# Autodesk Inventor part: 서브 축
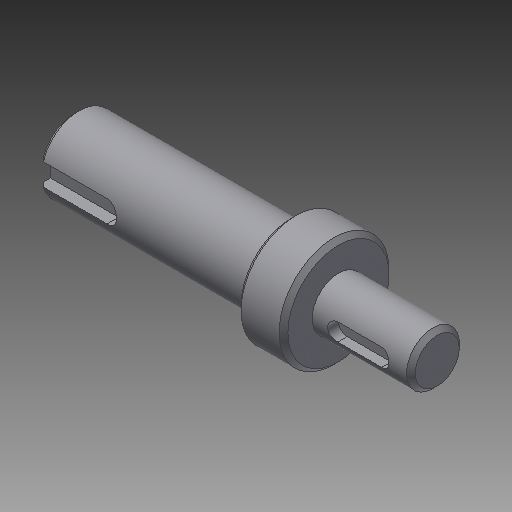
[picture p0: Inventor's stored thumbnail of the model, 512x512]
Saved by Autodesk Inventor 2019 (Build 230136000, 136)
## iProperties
Created: 2014-10
Part Number: 서브 축
Document SubType Name: Modeling
Designer: KYOUNG IL JANG
Density: 1 g/cm^3
Mass: 19.9624 g
Surface Area: 57.7178 cm^2
Volume: 19.9624 cm^3
Material: 강철, 연강
Appearance: 금속-강(스테인리스, 브러시됨)
Author: SeoGD™ [www.esajin.kr]
Revision Number: 1
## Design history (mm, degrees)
sketch "스케치1"
  geometry: L1 (-16.331, 0)-(-98.831, 0); L2 (-16.331, 0)-(-16.331, -6); L3 (-16.331, -6)-(-38.831, -6); L4 (-38.831, -12.5)-(-46.5, -12.5); L5 (-46.5, -8.5)-(-98.831, -8.5); L6 (-98.831, -8.5)-(-98.831, 0); L7 (-46.5, -8.5)-(-46.5, -12.5); L8 (-38.831, -6)-(-38.831, -12.5); L9 (-46.5, 12.249)-(-46.5, -12.249) reference; L10 (-38.831, -17)-(-38.831, 17) reference; 2 further points
  constraints: 17 end point, 4 perpendicular, 2 collinear, 2 parallel, 1 horizontal, 1 midpoint, 1 point on line
  dimensions: "d1" = 12 diameter of L3 L1; "d2" = 25 diameter of L4 L1; "d3" = 17 diameter of L5 L1; "d18" = 22.5 distance of L2.end L3.end; "d20" = 60 distance between parallel lines of L6 L8; "d21" = 7.66872 distance of L4.start L4.end (derived)
revolve "회전1" sketch "스케치1" stored, may be unused: angle "d5" = 90 deg
chamfer "모따기1" distance "d6" = 1; stored, may be unused: second distance "d7" = 2, angle "d8" = 45 deg
node "작업 평면1"
sketch "스케치2"
  geometry: L1 (11.25, 5)-(11.25, -5) reference; L2 (-5.75, -2)-(4.25, -2); L3 (4.25, 2)-(-5.75, 2); A1 r 2 centre (4.25, 0) between (4.25, -2) and (4.25, 2); A2 r 2 centre (-5.75, 0) between (-5.75, 2) and (-5.75, -2); 2 further points
  constraints: 4 end point, 4 point on circle, 4 tangent, 2 centre point, 1 horizontal alignment, 1 midpoint, 1 parallel, 1 perpendicular
  dimensions: "d9" = 4 distance between parallel lines of L2 L3; "d10" = 14 dimension on A1 A2; "d11" = 5 distance edge to line of A1 L1
extrude "돌출1" cut sketch "스케치2" distance "d12" = 2.5; taper "d13" = 0 deg
node "작업 평면2"
sketch "스케치3"
  geometry: L1 (-26.166, -7.5)-(-26.166, 7.5) reference; L2 (-26.166, 2.5)-(-10.666, 2.5); L3 (-10.666, -2.5)-(-26.166, -2.5); A1 r 2.5 centre (-10.666, 0) between (-10.666, -2.5) and (-10.666, 2.5); 2 further points
  constraints: 4 end point, 2 perpendicular, 2 point on circle, 2 point on line, 2 tangent, 1 centre point, 1 horizontal alignment, 1 midpoint
  dimensions: "d14" = 5 distance between parallel lines of L3 L2; "d15" = 18 dimension on A1 L1
extrude "돌출2" cut sketch "스케치3" distance "d16" = 3; taper "d17" = 0 deg
sketch "스케치4"
  geometry: C1 r 12.5 at (0, 0) reference; 1 further point
extrude "돌출3" join sketch "스케치4" distance "d22" = 3; taper "d23" = 0 deg
chamfer "모따기2" distance "d24" = 1; stored, may be unused: second distance "d25" = 2, angle "d26" = 45 deg
node "솔리드1"
node "참조4"
node "참조5"
